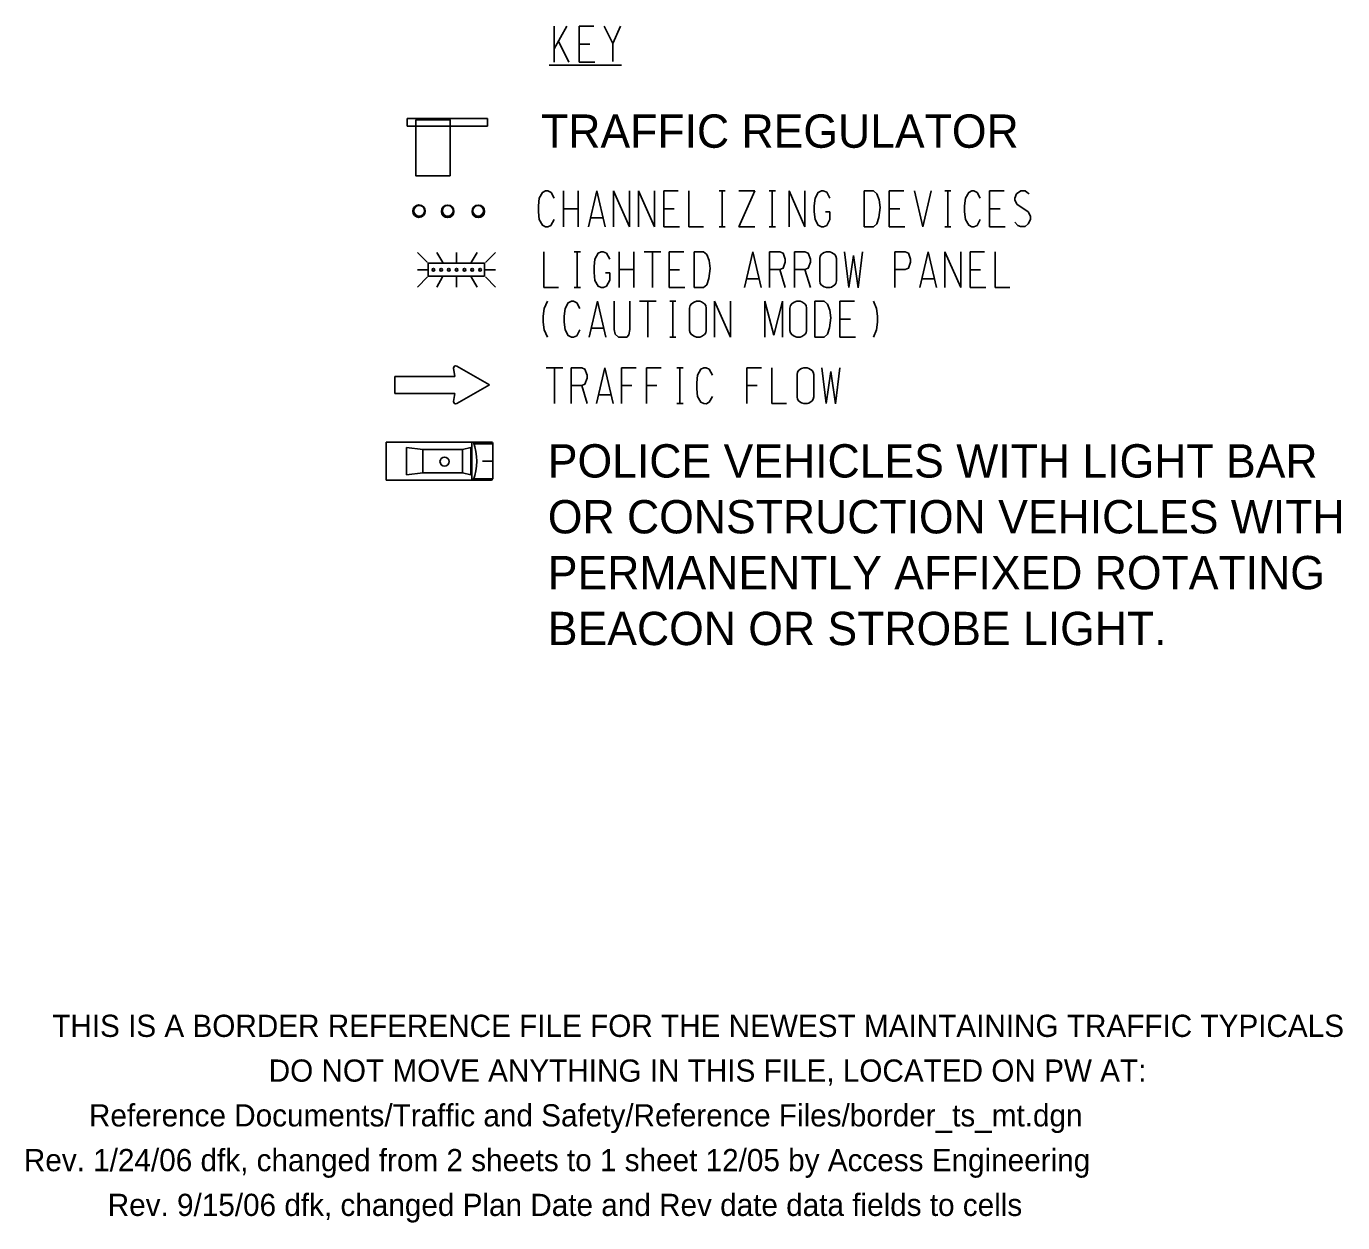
# Model space of a CAD drawing. Extents: x -1809 to 1554, y -1087 to 323.
# Drawn here: x -1808.8 to -1441.2, y -1086.6 to -752.5 of the extents above; entities that cross this region are included whole.
import ezdxf

# ---------------------------------------------------------------- set-up
doc = ezdxf.new("R2010")
doc.units = 0
for name, color, linetype in [('Level 1', 7, 'Continuous'), ('MT_SCRATCH_LEVEL_E', 7, 'Continuous'), ('MT_STAGE_1A_NOTES', 7, 'Continuous'), ('PAVT_EDGE_PR', 7, 'Continuous'), ('SCRATCH_LEVEL_A', 7, 'Continuous'), ('TRAFFIC_SIGNS_PR', 7, 'Continuous'), ('TYPICAL_TEXT_DIMEN_EX', 7, 'Continuous')]:
    doc.layers.add(name, color=color, linetype=linetype)

msp = doc.modelspace()

# ---------------------------------------------------------------- linework, layer by layer
at = {"layer": 'Level 1'}
for p, q in [((-1708.32, -879.3), (-1708.32, -868.67)), ((-1679.02, -868.67), (-1708.32, -868.67)), ((-1698.04, -870.74), (-1702.57, -870.18)), ((-1702.57, -870.18), (-1702.57, -877.79)), ((-1686.99, -870.74), (-1698.04, -870.74)), ((-1698.04, -870.74), (-1698.04, -877.23)), ((-1684.63, -870.18), (-1686.99, -870.74)), ((-1686.99, -870.74), (-1686.99, -877.23)), ((-1684.63, -877.79), (-1684.63, -870.18)), ((-1678.47, -869.3), (-1678.47, -869.16)), ((-1678.47, -869.18), (-1678.47, -869.17)), ((-1678.47, -878.88), (-1678.47, -869.3)), ((-1702.57, -877.79), (-1698.04, -877.23)), ((-1686.99, -877.23), (-1698.04, -877.23)), ((-1686.99, -877.23), (-1684.63, -877.79)), ((-1678.93, -879.3), (-1708.32, -879.3)), ((-1678.47, -878.94), (-1678.47, -878.8))]:
    msp.add_line(p, q, dxfattribs=at)
at = {"layer": 'MT_SCRATCH_LEVEL_E'}
for p, q in [((-1689.47, -848.03), (-1689.07, -850.28)), ((-1679.43, -852.62), (-1688.6, -847.42)), ((-1689.07, -850.28), (-1705.86, -850.28)), ((-1705.86, -850.28), (-1705.86, -855.02)), ((-1688.6, -857.88), (-1679.43, -852.62)), ((-1705.86, -855.02), (-1689.07, -855.02)), ((-1689.07, -855.02), (-1689.47, -857.27))]:
    msp.add_line(p, q, dxfattribs=at)
for centre, start, end in [((-1688.89, -847.93), 60.4248, 189.9638), ((-1688.89, -857.36), 170.0362, 299.7731)]:
    msp.add_arc(centre, 0.586, start, end, dxfattribs=at)
at = {"layer": 'MT_STAGE_1A_NOTES'}
for p, q in [((-1700.03, -778.64), (-1700.03, -794.25)), ((-1690.44, -778.64), (-1690.44, -794.25)), ((-1700.03, -794.25), (-1690.44, -794.25))]:
    msp.add_line(p, q, dxfattribs=at)
for points in [[(-1680.03, -778.31), (-1702.41, -778.31), (-1702.41, -780.41), (-1680.03, -780.41)], [(-1700.03, -778.64), (-1690.44, -778.64), (-1690.44, -794.25), (-1700.03, -794.25)]]:
    msp.add_lwpolyline(points, close=True, dxfattribs=at)
at = {"layer": 'PAVT_EDGE_PR'}
for p, q in [((-1684.34, -879.3), (-1684.34, -868.69)), ((-1678.47, -869.16), (-1683.77, -869.16)), ((-1678.47, -873.99), (-1681.35, -874)), ((-1678.47, -878.87), (-1683.81, -878.87))]:
    msp.add_line(p, q, dxfattribs=at)
for centre, radius in [((-1699.12, -804.13), 1.74), ((-1699.06, -804.04), 1.51), ((-1691.12, -804.21), 1.74), ((-1691.09, -804.04), 1.51), ((-1682.56, -804.21), 1.74), ((-1682.6, -804.04), 1.51), ((-1691.99, -874.07), 1.27)]:
    msp.add_circle(centre, radius, dxfattribs=at)
for centre, radius, start, end in [((-1698.58, -873.95), 15.57, 339.9375, 19.8442), ((-1678.94, -869.13), 0.469, 356.6455, 99.4095), ((-1678.93, -878.83), 0.469, 265.0608, 345.954)]:
    msp.add_arc(centre, radius, start, end, dxfattribs=at)
at = {"layer": 'TRAFFIC_SIGNS_PR'}
for p, q in [((-1699.58, -815.65), (-1696.76, -818.47)), ((-1692.5, -818.47), (-1694.12, -815.65)), ((-1688.68, -818.47), (-1688.68, -815.65)), ((-1684.54, -818.47), (-1682.92, -815.65)), ((-1680.59, -818.47), (-1677.77, -815.65)), ((-1696.76, -820.5), (-1699.58, -820.5)), ((-1699.58, -825.35), (-1696.76, -822.53)), ((-1695.13, -820.5), (-1695.13, -820.5)), ((-1694.15, -825.35), (-1692.52, -822.53)), ((-1692.95, -820.5), (-1692.95, -820.5)), ((-1690.78, -820.5), (-1690.78, -820.5)), ((-1688.68, -822.53), (-1688.68, -825.35)), ((-1688.6, -820.5), (-1688.6, -820.5)), ((-1686.43, -820.5), (-1686.43, -820.5)), ((-1682.89, -825.35), (-1684.52, -822.53)), ((-1684.26, -820.5), (-1684.26, -820.5)), ((-1682.09, -820.5), (-1682.09, -820.5)), ((-1680.59, -820.5), (-1677.77, -820.5)), ((-1680.59, -822.53), (-1677.77, -825.35))]:
    msp.add_line(p, q, dxfattribs=at)
msp.add_lwpolyline([(-1680.83, -822.3), (-1696.53, -822.3), (-1696.53, -818.7), (-1680.83, -818.7)], close=True, dxfattribs=at)
for centre in [(-1695.11, -820.5), (-1692.95, -820.5), (-1690.78, -820.5), (-1688.61, -820.5), (-1686.43, -820.5), (-1684.26, -820.5), (-1682.08, -820.5)]:
    msp.add_circle(centre, 0.379, dxfattribs=at)
at = {"layer": 'TYPICAL_TEXT_DIMEN_EX'}
msp.add_line((-1662.74, -763.37), (-1642.56, -763.37), dxfattribs=at)
for points in [[(-1661.38, -752.53), (-1661.38, -762.53)], [(-1661.38, -758.78), (-1657.88, -752.53)], [(-1650.29, -752.53), (-1654.38, -752.53)], [(-1654.38, -752.53), (-1654.38, -762.53)], [(-1647.38, -752.53), (-1645.04, -757.32)], [(-1645.04, -757.32), (-1642.86, -752.53)], [(-1660.21, -756.7), (-1657.29, -762.53)], [(-1651.46, -757.53), (-1654.38, -757.53)], [(-1645.04, -762.32), (-1645.04, -757.24)], [(-1654.38, -762.53), (-1650, -762.53)], [(-1665.53, -800.53), (-1665.78, -802.67), (-1665.78, -804.33), (-1665.53, -806.47)], [(-1662.26, -798.89), (-1663.18, -798.5), (-1663.76, -798.5), (-1664.63, -798.89), (-1665.53, -800.53)], [(-1661.39, -800.53), (-1662.26, -798.89)], [(-1658.8, -798.5), (-1658.8, -808.5)], [(-1654.72, -808.5), (-1654.72, -798.5)], [(-1651.8, -808.5), (-1649.47, -798.5)], [(-1649.47, -798.5), (-1647.13, -808.5)], [(-1644.8, -808.5), (-1644.8, -798.5)], [(-1644.8, -798.5), (-1640.39, -808.5)], [(-1640.39, -808.5), (-1640.39, -798.5)], [(-1637.8, -808.5), (-1637.8, -798.5)], [(-1637.8, -798.5), (-1633.39, -808.5)], [(-1633.39, -808.5), (-1633.39, -798.5)], [(-1626.72, -798.5), (-1630.8, -798.5)], [(-1630.8, -798.5), (-1630.8, -808.5)], [(-1623.8, -798.5), (-1623.8, -808.5)], [(-1615.34, -798.5), (-1613.59, -798.5)], [(-1614.47, -798.5), (-1614.47, -808.5)], [(-1609.8, -798.5), (-1605.39, -798.5)], [(-1605.39, -798.5), (-1609.8, -808.5)], [(-1601.34, -798.5), (-1599.59, -798.5)], [(-1600.47, -798.5), (-1600.47, -808.5)], [(-1595.8, -808.5), (-1595.8, -798.5)], [(-1595.8, -798.5), (-1591.39, -808.5)], [(-1591.39, -808.5), (-1591.39, -798.5)], [(-1588.53, -800.53), (-1588.78, -802.64), (-1588.79, -804.31), (-1588.53, -806.47)], [(-1585.26, -798.87), (-1586.23, -798.5), (-1586.77, -798.5), (-1587.63, -798.89), (-1588.53, -800.53)], [(-1584.39, -800.53), (-1585.26, -798.87)], [(-1572.18, -798.5), (-1574.8, -798.5)], [(-1574.8, -798.5), (-1574.8, -808.5)], [(-1572.18, -798.5), (-1571.26, -799.28), (-1570.66, -800.95), (-1570.35, -803.16), (-1570.7, -805.92), (-1571.3, -807.69), (-1572.18, -808.5)], [(-1563.72, -798.5), (-1567.8, -798.5)], [(-1567.8, -798.5), (-1567.8, -808.5)], [(-1560.8, -798.5), (-1558.47, -808.5)], [(-1558.47, -808.5), (-1556.13, -798.5)], [(-1552.34, -798.5), (-1550.59, -798.5)], [(-1551.47, -798.5), (-1551.47, -808.5)], [(-1546.53, -800.53), (-1546.78, -802.67), (-1546.78, -804.33), (-1546.53, -806.47)], [(-1543.26, -798.89), (-1544.18, -798.5), (-1544.76, -798.5), (-1545.63, -798.89), (-1546.53, -800.53)], [(-1542.39, -800.53), (-1543.26, -798.89)], [(-1535.72, -798.5), (-1539.8, -798.5)], [(-1539.8, -798.5), (-1539.8, -808.5)], [(-1532.25, -799.28), (-1532.78, -800.53), (-1532.79, -800.95), (-1532.24, -802.2)], [(-1529.3, -798.89), (-1529.87, -798.5), (-1531.05, -798.5), (-1532.25, -799.28)], [(-1529.3, -798.89), (-1528.72, -799.28)], [(-1658.8, -803.45), (-1654.72, -803.45)], [(-1627.88, -803.5), (-1630.8, -803.5)], [(-1585.59, -804.33), (-1584.37, -804.33)], [(-1584.37, -804.33), (-1584.37, -806.44)], [(-1564.88, -803.5), (-1567.8, -803.5)], [(-1536.88, -803.5), (-1539.8, -803.5)], [(-1532.24, -802.2), (-1528.99, -804.33)], [(-1528.99, -807.72), (-1528.4, -806.45), (-1528.4, -805.58), (-1528.99, -804.33)], [(-1665.53, -806.47), (-1664.63, -808.08), (-1663.76, -808.51), (-1663.16, -808.53), (-1662.28, -808.14)], [(-1661.39, -806.47), (-1662.28, -808.14)], [(-1647.72, -806), (-1651.22, -806)], [(-1630.8, -808.5), (-1626.43, -808.5)], [(-1623.8, -808.5), (-1619.72, -808.5)], [(-1615.34, -808.5), (-1613.59, -808.5)], [(-1609.8, -808.5), (-1605.39, -808.5)], [(-1601.34, -808.5), (-1599.59, -808.5)], [(-1588.53, -806.47), (-1587.65, -808.06), (-1586.76, -808.5), (-1586.16, -808.49), (-1585.26, -808.11)], [(-1584.37, -806.44), (-1585.26, -808.11)], [(-1574.8, -808.5), (-1572.18, -808.5)], [(-1567.8, -808.5), (-1563.43, -808.5)], [(-1552.34, -808.5), (-1550.59, -808.5)], [(-1546.53, -806.47), (-1545.63, -808.08), (-1544.76, -808.51), (-1544.16, -808.53), (-1543.28, -808.14)], [(-1542.39, -806.47), (-1543.28, -808.14)], [(-1539.8, -808.5), (-1535.43, -808.5)], [(-1532.8, -807.25), (-1531.91, -808.14)], [(-1531.91, -808.14), (-1531.18, -808.46), (-1529.88, -808.45), (-1528.99, -807.72)], [(-1664.27, -815.5), (-1664.27, -825.5)], [(-1655.81, -815.5), (-1654.06, -815.5)], [(-1654.93, -815.5), (-1654.93, -825.5)], [(-1646.73, -815.87), (-1647.7, -815.5), (-1648.24, -815.5), (-1649.1, -815.89), (-1649.99, -817.53)], [(-1645.85, -817.53), (-1646.73, -815.87)], [(-1643.27, -815.5), (-1643.27, -825.5)], [(-1639.18, -825.5), (-1639.18, -815.5)], [(-1636.27, -815.5), (-1631.6, -815.5)], [(-1633.93, -815.5), (-1633.93, -825.5)], [(-1625.18, -815.5), (-1629.27, -815.5)], [(-1629.27, -815.5), (-1629.27, -825.5)], [(-1619.64, -815.5), (-1622.27, -815.5)], [(-1622.27, -815.5), (-1622.27, -825.5)], [(-1619.64, -815.5), (-1618.73, -816.28), (-1618.13, -817.95), (-1617.81, -820.16), (-1618.17, -822.92), (-1618.77, -824.69), (-1619.64, -825.5)], [(-1608.27, -825.5), (-1605.93, -815.5)], [(-1605.93, -815.5), (-1603.6, -825.5)], [(-1601.27, -825.5), (-1601.27, -815.5)], [(-1601.27, -815.5), (-1598.35, -815.5)], [(-1598.35, -815.5), (-1597.48, -815.92), (-1596.85, -817.53), (-1596.85, -818.42), (-1597.48, -820.08), (-1598.35, -820.45)], [(-1594.27, -825.5), (-1594.27, -815.5)], [(-1594.27, -815.5), (-1591.35, -815.5)], [(-1591.35, -815.5), (-1590.48, -815.92), (-1589.85, -817.53), (-1589.85, -818.42), (-1590.48, -820.08), (-1591.35, -820.45)], [(-1587.24, -817.38), (-1587.08, -816.7), (-1586.72, -816.2), (-1586, -815.72), (-1585.31, -815.5), (-1584.38, -815.5), (-1583.92, -815.68), (-1583.04, -816.25), (-1582.73, -816.7), (-1582.57, -817.38)], [(-1580.27, -815.5), (-1579.1, -825.5)], [(-1576.48, -825.53), (-1575.25, -815.5)], [(-1566.27, -825.5), (-1566.27, -815.5)], [(-1566.27, -815.5), (-1563.35, -815.5)], [(-1563.35, -815.5), (-1562.48, -815.92), (-1561.85, -817.53), (-1561.85, -818.42), (-1562.48, -820.08), (-1563.35, -820.45)], [(-1559.27, -825.5), (-1556.93, -815.5)], [(-1556.93, -815.5), (-1554.6, -825.5)], [(-1552.27, -825.5), (-1552.27, -815.5)], [(-1552.27, -815.5), (-1547.85, -825.5)], [(-1547.85, -825.5), (-1547.85, -815.5)], [(-1541.18, -815.5), (-1545.27, -815.5)], [(-1545.27, -815.5), (-1545.27, -825.5)], [(-1538.27, -815.5), (-1538.27, -825.5)], [(-1649.99, -817.53), (-1650.25, -819.64), (-1650.25, -821.31), (-1649.99, -823.47)], [(-1587.24, -823.63), (-1587.24, -817.38)], [(-1582.57, -823.63), (-1582.57, -817.38)], [(-1579.1, -825.5), (-1577.77, -816.5)], [(-1577.77, -816.5), (-1576.48, -825.53)], [(-1647.06, -821.33), (-1645.84, -821.33)], [(-1645.84, -821.33), (-1645.84, -823.44)], [(-1643.27, -820.45), (-1639.18, -820.45)], [(-1626.35, -820.5), (-1629.27, -820.5)], [(-1604.18, -823), (-1607.68, -823)], [(-1598.35, -820.45), (-1601.27, -820.45)], [(-1598.35, -820.45), (-1596.85, -825.5)], [(-1591.35, -820.45), (-1594.27, -820.45)], [(-1591.35, -820.45), (-1589.85, -825.5)], [(-1563.35, -820.45), (-1566.27, -820.45)], [(-1555.18, -823), (-1558.68, -823)], [(-1542.35, -820.5), (-1545.27, -820.5)], [(-1664.27, -825.5), (-1660.18, -825.5)], [(-1655.81, -825.5), (-1654.06, -825.5)], [(-1649.99, -823.47), (-1649.12, -825.06), (-1648.23, -825.5), (-1647.62, -825.49), (-1646.73, -825.11)], [(-1645.84, -823.44), (-1646.73, -825.11)], [(-1629.27, -825.5), (-1624.89, -825.5)], [(-1622.27, -825.5), (-1619.64, -825.5)], [(-1587.24, -823.63), (-1587.08, -824.3), (-1586.72, -824.8), (-1586, -825.28), (-1585.31, -825.5), (-1584.38, -825.5), (-1583.92, -825.33), (-1583.04, -824.75), (-1582.73, -824.3), (-1582.57, -823.63)], [(-1545.27, -825.5), (-1540.89, -825.5)], [(-1538.27, -825.5), (-1534.18, -825.5)], [(-1663.26, -829.31), (-1664.15, -831.35), (-1664.43, -833.48), (-1664.43, -835.15), (-1664.15, -837.28), (-1663.26, -839.31)], [(-1655.06, -829.71), (-1655.97, -829.31), (-1656.55, -829.31), (-1657.43, -829.71), (-1658.32, -831.35)], [(-1654.18, -831.35), (-1655.06, -829.71)], [(-1651.59, -839.31), (-1649.26, -829.31)], [(-1649.26, -829.31), (-1646.93, -839.31)], [(-1644.59, -829.31), (-1644.59, -837.23)], [(-1640.22, -837.23), (-1640.22, -829.31)], [(-1637.59, -829.31), (-1632.93, -829.31)], [(-1635.26, -829.31), (-1635.26, -839.31)], [(-1629.13, -829.31), (-1627.38, -829.31)], [(-1628.26, -829.31), (-1628.26, -839.31)], [(-1623.56, -831.19), (-1623.41, -830.52), (-1623.05, -830.02), (-1622.33, -829.54), (-1621.64, -829.31), (-1620.7, -829.31), (-1620.24, -829.49), (-1619.36, -830.06), (-1619.05, -830.52), (-1618.9, -831.19)], [(-1616.59, -839.31), (-1616.59, -829.31)], [(-1616.59, -829.31), (-1612.18, -839.31)], [(-1612.18, -839.31), (-1612.18, -829.31)], [(-1602.59, -839.31), (-1602.59, -829.31)], [(-1602.59, -829.31), (-1600.08, -838.76)], [(-1600.08, -838.76), (-1597.6, -829.31)], [(-1597.6, -829.31), (-1597.58, -839.31)], [(-1595.56, -831.19), (-1595.41, -830.52), (-1595.05, -830.02), (-1594.33, -829.54), (-1593.64, -829.31), (-1592.7, -829.31), (-1592.24, -829.49), (-1591.36, -830.06), (-1591.05, -830.52), (-1590.9, -831.19)], [(-1585.97, -829.31), (-1588.59, -829.31)], [(-1588.59, -829.31), (-1588.59, -839.31)], [(-1585.97, -829.31), (-1585.06, -830.1), (-1584.45, -831.76), (-1584.14, -833.97), (-1584.49, -836.74), (-1585.09, -838.51), (-1585.97, -839.31)], [(-1577.51, -829.31), (-1581.59, -829.31)], [(-1581.59, -829.31), (-1581.59, -839.31)], [(-1572.26, -829.32), (-1571.37, -831.35), (-1571.09, -833.48), (-1571.09, -835.15), (-1571.37, -837.28), (-1572.26, -839.31)], [(-1658.32, -831.35), (-1658.57, -833.48), (-1658.57, -835.15), (-1658.32, -837.28)], [(-1623.56, -837.44), (-1623.56, -831.19)], [(-1618.9, -837.44), (-1618.9, -831.19)], [(-1595.56, -837.44), (-1595.56, -831.19)], [(-1590.9, -837.44), (-1590.9, -831.19)], [(-1658.32, -837.28), (-1657.43, -838.9), (-1656.55, -839.32), (-1655.95, -839.34), (-1655.07, -838.95)], [(-1654.18, -837.28), (-1655.07, -838.95)], [(-1647.51, -836.81), (-1651.01, -836.81)], [(-1640.22, -837.23), (-1640.51, -838.69), (-1641.09, -839.31), (-1643.43, -839.31), (-1644.32, -838.53), (-1644.59, -837.23)], [(-1623.56, -837.44), (-1623.41, -838.11), (-1623.05, -838.61), (-1622.33, -839.09), (-1621.64, -839.31), (-1620.7, -839.31), (-1620.24, -839.14), (-1619.36, -838.56), (-1619.05, -838.11), (-1618.9, -837.44)], [(-1595.56, -837.44), (-1595.41, -838.11), (-1595.05, -838.61), (-1594.33, -839.09), (-1593.64, -839.31), (-1592.7, -839.31), (-1592.24, -839.14), (-1591.36, -838.56), (-1591.05, -838.11), (-1590.9, -837.44)], [(-1578.68, -834.31), (-1581.59, -834.31)], [(-1629.13, -839.31), (-1627.38, -839.31)], [(-1588.59, -839.31), (-1585.97, -839.31)], [(-1581.59, -839.31), (-1577.22, -839.31)], [(-1663.6, -847.89), (-1658.93, -847.89)], [(-1661.26, -847.89), (-1661.26, -857.89)], [(-1656.6, -857.89), (-1656.6, -847.89)], [(-1656.6, -847.89), (-1653.68, -847.89)], [(-1653.68, -847.89), (-1652.81, -848.31), (-1652.19, -849.93), (-1652.19, -850.81), (-1652.81, -852.48), (-1653.68, -852.84)], [(-1649.6, -857.89), (-1647.26, -847.89)], [(-1647.26, -847.89), (-1644.93, -857.89)], [(-1638.51, -847.89), (-1642.6, -847.89)], [(-1642.6, -847.89), (-1642.6, -857.89)], [(-1631.51, -847.89), (-1635.6, -847.89)], [(-1635.6, -847.89), (-1635.6, -857.89)], [(-1627.14, -847.89), (-1625.39, -847.89)], [(-1626.26, -847.89), (-1626.26, -857.89)], [(-1618.06, -848.28), (-1618.97, -847.89), (-1619.56, -847.89), (-1620.43, -848.28), (-1621.32, -849.93)], [(-1617.19, -849.93), (-1618.06, -848.28)], [(-1603.51, -847.89), (-1607.6, -847.89)], [(-1607.6, -847.89), (-1607.6, -857.89)], [(-1600.6, -847.89), (-1600.6, -857.89)], [(-1593.57, -849.77), (-1593.41, -849.1), (-1593.05, -848.59), (-1592.34, -848.11), (-1591.64, -847.89), (-1590.71, -847.89), (-1590.25, -848.07), (-1589.37, -848.64), (-1589.06, -849.1), (-1588.9, -849.77)], [(-1586.6, -847.89), (-1585.43, -857.89)], [(-1585.43, -857.89), (-1584.1, -848.9)], [(-1584.1, -848.9), (-1582.81, -857.92)], [(-1582.81, -857.92), (-1581.58, -847.89)], [(-1621.32, -849.93), (-1621.58, -852.06), (-1621.58, -853.73), (-1621.32, -855.86)], [(-1593.57, -856.02), (-1593.57, -849.77)], [(-1588.9, -856.02), (-1588.9, -849.77)], [(-1653.68, -852.84), (-1656.6, -852.84)], [(-1653.68, -852.84), (-1652.19, -857.89)], [(-1645.51, -855.39), (-1649.01, -855.39)], [(-1642.6, -852.84), (-1639.7, -852.84)], [(-1635.6, -852.84), (-1632.7, -852.84)], [(-1621.32, -855.86), (-1620.43, -857.48), (-1619.55, -857.9), (-1618.95, -857.92), (-1618.08, -857.53)], [(-1617.19, -855.86), (-1618.08, -857.53)], [(-1607.6, -852.84), (-1604.7, -852.84)], [(-1593.57, -856.02), (-1593.41, -856.69), (-1593.05, -857.19), (-1592.34, -857.67), (-1591.64, -857.89), (-1590.71, -857.89), (-1590.25, -857.72), (-1589.37, -857.14), (-1589.06, -856.69), (-1588.9, -856.02)], [(-1627.14, -857.89), (-1625.39, -857.89)], [(-1600.6, -857.89), (-1596.51, -857.89)]]:
    msp.add_lwpolyline(points, dxfattribs=at)

# ---------------------------------------------------------------- texts
at = {"layer": 'SCRATCH_LEVEL_A'}
for s, p in [('THIS IS A BORDER REFERENCE FILE FOR THE NEWEST MAINTAINING TRAFFIC TYPICALS', (-1801.53, -1034.74)), ('DO NOT MOVE ANYTHING IN THIS FILE, LOCATED ON PW AT:', (-1741.09, -1047.24)), ('Reference Documents/Traffic and Safety/Reference Files/border_ts_mt.dgn', (-1791.27, -1059.74)), ('Rev. 1/24/06 dfk, changed from 2 sheets to 1 sheet 12/05 by Access Engineering', (-1809.44, -1072.24)), ('Rev. 9/15/06 dfk, changed Plan Date and Rev date data fields to cells', (-1786.03, -1084.74))]:
    msp.add_text(s, height=6.2, dxfattribs=at).set_placement(p)
at = {"layer": 'TYPICAL_TEXT_DIMEN_EX'}
for s, p in [('TRAFFIC REGULATOR', (-1665.03, -786.44)), ('POLICE VEHICLES WITH LIGHT BAR ', (-1663.15, -878.53)), ('OR CONSTRUCTION VEHICLES WITH ', (-1663.15, -894.13)), ('PERMANENTLY AFFIXED ROTATING ', (-1663.15, -909.73)), ('BEACON OR STROBE LIGHT.', (-1663.15, -925.33))]:
    msp.add_text(s, height=9.3, dxfattribs=at).set_placement(p)

doc.saveas('drawing.dxf')
